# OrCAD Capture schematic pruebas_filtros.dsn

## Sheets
1 orden 5: size A
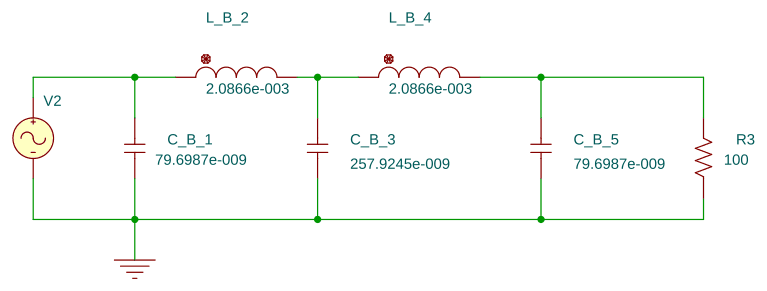
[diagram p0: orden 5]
2 PAGE1: size A
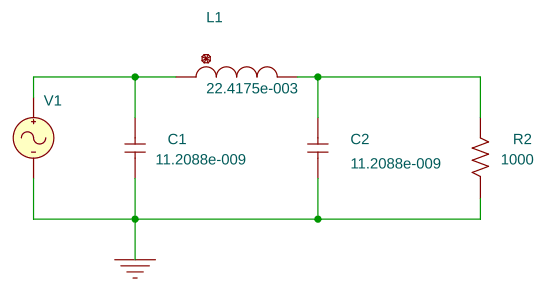
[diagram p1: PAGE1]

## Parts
sheet orden 5
C_B_1  79.6987e-009  [RAD/CK05]
C_B_3  257.9245e-009  [RAD/CK05]
C_B_5  79.6987e-009  [RAD/CK05]
L_B_2  2.0866e-003  [DISC/.350x.175/LS.200x.100/.034]
L_B_4  2.0866e-003  [DISC/.350x.175/LS.200x.100/.034]
R3  100  [AX/RC05]
V2  VAC
sheet PAGE1
C1  11.2088e-009  [RAD/CK05]
C2  11.2088e-009  [RAD/CK05]
L1  22.4175e-003  [DISC/.350x.175/LS.200x.100/.034]
R2  1000  [AX/RC05]
V1  VAC

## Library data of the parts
C1 C2 C_B_1 C_B_3 C_B_5 = C
L1 L_B_2 L_B_4 = L
R2 R3 = R
V1 V2 = VAC

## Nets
0: C1.1 C2.1 C_B_1.1 C_B_3.1 C_B_5.1 R2.1 R3.1 V1.2(-) V2.2(-)
N14428: C1.2 L1.1 V1.1(+)
N14459: C2.2 L1.2 R2.2
N15377: C_B_1.2 L_B_2.1 V2.1(+)
N15397: C_B_3.2 L_B_2.2 L_B_4.1
N15411: C_B_5.2 L_B_4.2 R3.2
